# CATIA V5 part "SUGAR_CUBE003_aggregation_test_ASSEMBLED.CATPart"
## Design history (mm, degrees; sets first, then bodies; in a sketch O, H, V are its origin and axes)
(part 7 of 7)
Relations
  design table, configuration 1, drives Body2.X1, Body2.X2, Body2.Y1, Body2.Y2, Body2.Z1, Body2.Z2, Body2.4_sided_dice, Body2.random_density, Body3.X1, Body3.X2, Body3.Y1, Body3.Y2, Body3.Z1, Body3.Z2, Body3.4_sided_dice, Body3.random_density, Body4.X1, Body4.X2, Body4.Y1, Body4.Y2, Body4.Z1, Body4.Z2, Body4.4_sided_dice, Body4.random_density, Body5.X1, Body5.X2, Body5.Y1, Body5.Y2, Body5.Z1, Body5.Z2, Body5.4_sided_dice, Body5.random_density, Body6.X1, Body6.X2, Body6.Y1, Body6.Y2, Body6.Z1, Body6.Z2, Body6.4_sided_dice, Body6.random_density, Body7.X1, Body7.X2, Body7.Y1, Body7.Y2, Body7.Z1, Body7.Z2, Body7.4_sided_dice, Body7.random_density, Body8.X1, Body8.X2, Body8.Y1, Body8.Y2, Body8.Z1, Body8.Z2, Body8.4_sided_dice, Body8.random_density, Body9.X1, Body9.X2, Body9.Y1, Body9.Y2, Body9.Z1, Body9.Z2, Body9.4_sided_dice, Body9.random_density, Body10.X1, Body10.X2, Body10.Y1, Body10.Y2, Body10.Z1, Body10.Z2, Body10.4_sided_dice, Body10.random_density, Body11.X1, Body11.X2, Body11.Y1, Body11.Y2, Body11.Z1, Body11.Z2, Body11.4_sided_dice, Body11.random_density, Body12.X1, Body12.X2, Body12.Y1, Body12.Y2, Body12.Z1, Body12.Z2, Body12.4_sided_dice, Body12.random_density, Body13.X1, Body13.X2, Body13.Y1, Body13.Y2, Body13.Z1, Body13.Z2, Body13.4_sided_dice, Body13.random_density, Body14.X1, Body14.X2, Body14.Y1, Body14.Y2, Body14.Z1, Body14.Z2, Body14.4_sided_dice, Body14.random_density, Body15.X1, Body15.X2, Body15.Y1, Body15.Y2, Body15.Z1, Body15.Z2, Body15.4_sided_dice, Body15.random_density, Body16.X1, Body16.X2, Body16.Y1, Body16.Y2, Body16.Z1, Body16.Z2, Body16.4_sided_dice, Body16.random_density, Body17.X1, Body17.X2, Body17.Y1, Body17.Y2, Body17.Z1, Body17.Z2, Body17.4_sided_dice, Body17.random_density, Body18.X1, Body18.X2, Body18.Y1, Body18.Y2, Body18.Z1, Body18.Z2, Body18.4_sided_dice, Body18.random_density, Body19.X1, Body19.X2, Body19.Y1, Body19.Y2, Body19.Z1, Body19.Z2, Body19.4_sided_dice, Body19.random_density, Body20.X1, Body20.X2, Body20.Y1, Body20.Y2, Body20.Z1, Body20.Z2, Body20.4_sided_dice, Body20.random_density, Body21.X1, Body21.X2, Body21.Y1, Body21.Y2, Body21.Z1, Body21.Z2, Body21.4_sided_dice, Body21.random_density, Body22.X1, Body22.X2, Body22.Y1, Body22.Y2, Body22.Z1, Body22.Z2, Body22.4_sided_dice, Body22.random_density, Body23.X1, Body23.X2, Body23.Y1, Body23.Y2, Body23.Z1, Body23.Z2, Body23.4_sided_dice, Body23.random_density, Body24.X1, Body24.X2, Body24.Y1, Body24.Y2, Body24.Z1, Body24.Z2, Body24.4_sided_dice, Body24.random_density, Body25.X1, Body25.X2, Body25.Y1, Body25.Y2, Body25.Z1, Body25.Z2, Body25.4_sided_dice, Body25.random_density, Body26.X1, Body26.X2, Body26.Y1, Body26.Y2, Body26.Z1, Body26.Z2, Body26.4_sided_dice, Body26.random_density, Body27.X1, Body27.X2, Body27.Y1, Body27.Y2, Body27.Z1, Body27.Z2, Body27.4_sided_dice, Body27.random_density, Body28.X1, Body28.X2, Body28.Y1, Body28.Y2, Body28.Z1, Body28.Z2, Body28.4_sided_dice, Body28.random_density, Body29.X1, Body29.X2, Body29.Y1, Body29.Y2, Body29.Z1, Body29.Z2, Body29.4_sided_dice, Body29.random_density, Body30.X1, Body30.X2, Body30.Y1, Body30.Y2, Body30.Z1, Body30.Z2, Body30.4_sided_dice, Body30.random_density, Body31.X1, Body31.X2, Body31.Y1, Body31.Y2, Body31.Z1, Body31.Z2, Body31.4_sided_dice, Body31.random_density, Body32.X1, Body32.X2, Body32.Y1, Body32.Y2, Body32.Z1, Body32.Z2, Body32.4_sided_dice, Body32.random_density, Body33.X1, Body33.X2, Body33.Y1, Body33.Y2, Body33.Z1, Body33.Z2, Body33.4_sided_dice, Body33.random_density, Body34.X1, Body34.X2, Body34.Y1, Body34.Y2, Body34.Z1, Body34.Z2, Body34.4_sided_dice, Body34.random_density, Body35.X1, Body35.X2, Body35.Y1, Body35.Y2, Body35.Z1, Body35.Z2, Body35.4_sided_dice, Body35.random_density, Body36.X1, Body36.X2, Body36.Y1, Body36.Y2, Body36.Z1, Body36.Z2, Body36.4_sided_dice, Body36.random_density, Body37.X1, Body37.X2, Body37.Y1, Body37.Y2, Body37.Z1, Body37.Z2, Body37.4_sided_dice, Body37.random_density, Body38.X1, Body38.X2, Body38.Y1, Body38.Y2, Body38.Z1, Body38.Z2, Body38.4_sided_dice, Body38.random_density, Body39.X1, Body39.X2, Body39.Y1, Body39.Y2, Body39.Z1, Body39.Z2, Body39.4_sided_dice, Body39.random_density, Body40.X1, Body40.X2, Body40.Y1, Body40.Y2, Body40.Z1, Body40.Z2, Body40.4_sided_dice, Body40.random_density, Body41.X1, Body41.X2, Body41.Y1, Body41.Y2, Body41.Z1, Body41.Z2, Body41.4_sided_dice, Body41.random_density, Body42.X1, Body42.X2, Body42.Y1, Body42.Y2, Body42.Z1, Body42.Z2, Body42.4_sided_dice, Body42.random_density, Body43.X1, Body43.X2, Body43.Y1, Body43.Y2, Body43.Z1, Body43.Z2, Body43.4_sided_dice, Body43.random_density, Body44.X1, Body44.X2, Body44.Y1, Body44.Y2, Body44.Z1, Body44.Z2, Body44.4_sided_dice, Body44.random_density, Body45.X1, Body45.X2, Body45.Y1, Body45.Y2, Body45.Z1, Body45.Z2, Body45.4_sided_dice, Body45.random_density, Body46.X1, Body46.X2, Body46.Y1, Body46.Y2, Body46.Z1, Body46.Z2, Body46.4_sided_dice, Body46.random_density, Body47.X1, Body47.X2, Body47.Y1, Body47.Y2, Body47.Z1, Body47.Z2, Body47.4_sided_dice, Body47.random_density, Body48.X1, Body48.X2, Body48.Y1, Body48.Y2, Body48.Z1, Body48.Z2, Body48.4_sided_dice, Body48.random_density, Body49.X1, Body49.X2, Body49.Y1, Body49.Y2, Body49.Z1, Body49.Z2, Body49.4_sided_dice, Body49.random_density, Body50.X1, Body50.X2, Body50.Y1, Body50.Y2, Body50.Z1, Body50.Z2, Body50.4_sided_dice, Body50.random_density, Body51.X1, Body51.X2, Body51.Y1, Body51.Y2, Body51.Z1, Body51.Z2, Body51.4_sided_dice, Body51.random_density, Body52.X1, Body52.X2, Body52.Y1, Body52.Y2, Body52.Z1, Body52.Z2, Body52.4_sided_dice, Body52.random_density, Body53.X1, Body53.X2, Body53.Y1, Body53.Y2, Body53.Z1, Body53.Z2, Body53.4_sided_dice, Body53.random_density, Body54.X1, Body54.X2, Body54.Y1, Body54.Y2, Body54.Z1, Body54.Z2, Body54.4_sided_dice, Body54.random_density, Body55.X1, Body55.X2, Body55.Y1, Body55.Y2, Body55.Z1, Body55.Z2, Body55.4_sided_dice, Body55.random_density, Body56.X1, Body56.X2, Body56.Y1, Body56.Y2, Body56.Z1, Body56.Z2, Body56.4_sided_dice, Body56.random_density, Body57.X1, Body57.X2, Body57.Y1, Body57.Y2, Body57.Z1, Body57.Z2, Body57.4_sided_dice, Body57.random_density, Body58.X1, Body58.X2, Body58.Y1, Body58.Y2, Body58.Z1, Body58.Z2, Body58.4_sided_dice, Body58.random_density, Body59.X1, Body59.X2, Body59.Y1, Body59.Y2, Body59.Z1, Body59.Z2, Body59.4_sided_dice, Body59.random_density, Body60.X1, Body60.X2, Body60.Y1, Body60.Y2, Body60.Z1, Body60.Z2, Body60.4_sided_dice, Body60.random_density, Body61.X1, Body61.X2, Body61.Y1, Body61.Y2, Body61.Z1, Body61.Z2, Body61.4_sided_dice, Body61.random_density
